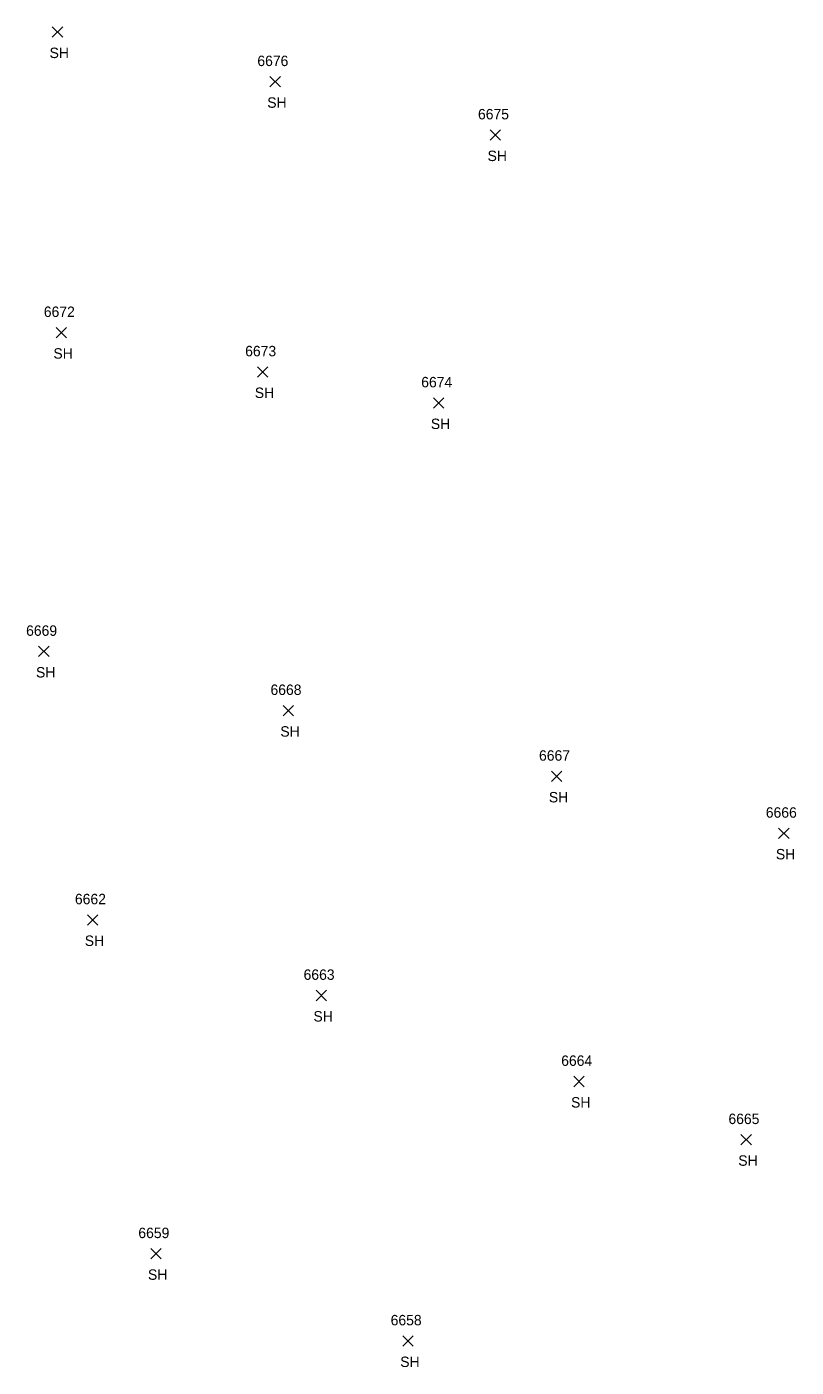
# Model space of a CAD drawing. Extents: x 1678863 to 1683592, y 407783 to 418211.
# Drawn here: x 1679579.6 to 1679727.2, y 410040.3 to 410297.6 of the extents above; entities that cross this region are included whole.
import ezdxf

# ---------------------------------------------------------------- set-up
doc = ezdxf.new("R2010")
doc.units = 0
for name, color, linetype in [('L_A', 7, 'Continuous'), ('L_I', 7, 'Continuous'), ('L_TIC', 7, 'Continuous')]:
    doc.layers.add(name, color=color, linetype=linetype)

msp = doc.modelspace()

# ---------------------------------------------------------------- linework, layer by layer
at = {"layer": 'L_TIC'}
for points in [[(1679584.46, 410295.56), (1679586.46, 410297.56)], [(1679586.46, 410295.56), (1679584.46, 410297.56)], [(1679626.23, 410286.02), (1679628.23, 410288.02)], [(1679628.23, 410286.02), (1679626.23, 410288.02)], [(1679668.51, 410275.79), (1679670.51, 410277.79)], [(1679670.51, 410275.79), (1679668.51, 410277.79)], [(1679585.19, 410237.87), (1679587.19, 410239.87)], [(1679587.19, 410237.87), (1679585.19, 410239.87)], [(1679623.84, 410230.32), (1679625.84, 410232.32)], [(1679625.84, 410230.32), (1679623.84, 410232.32)], [(1679657.62, 410224.36), (1679659.62, 410226.36)], [(1679659.62, 410224.36), (1679657.62, 410226.36)], [(1679581.85, 410176.67), (1679583.85, 410178.67)], [(1679583.85, 410176.67), (1679581.85, 410178.67)], [(1679628.75, 410165.32), (1679630.75, 410167.32)], [(1679630.75, 410165.32), (1679628.75, 410167.32)], [(1679680.27, 410152.7), (1679682.27, 410154.7)], [(1679682.27, 410152.7), (1679680.27, 410154.7)], [(1679723.85, 410141.76), (1679725.85, 410143.76)], [(1679725.85, 410141.76), (1679723.85, 410143.76)], [(1679591.21, 410125.15), (1679593.21, 410127.15)], [(1679593.21, 410125.15), (1679591.21, 410127.15)], [(1679635.09, 410110.64), (1679637.09, 410112.64)], [(1679637.09, 410110.64), (1679635.09, 410112.64)], [(1679684.53, 410094.13), (1679686.53, 410096.13)], [(1679686.53, 410094.13), (1679684.53, 410096.13)], [(1679716.63, 410082.96), (1679718.63, 410084.96)], [(1679718.63, 410082.96), (1679716.63, 410084.96)], [(1679603.35, 410061.07), (1679605.35, 410063.07)], [(1679605.35, 410061.07), (1679603.35, 410063.07)], [(1679651.75, 410044.33), (1679653.75, 410046.33)], [(1679653.75, 410044.33), (1679651.75, 410046.33)]]:
    msp.add_lwpolyline(points, dxfattribs=at)

# ---------------------------------------------------------------- texts
at = {"layer": 'L_A'}
for p in [(1679583.95, 410291.56), (1679625.72, 410282.02), (1679668, 410271.79), (1679584.68, 410233.87), (1679623.33, 410226.32), (1679657.11, 410220.36), (1679581.34, 410172.67), (1679628.23, 410161.32), (1679679.76, 410148.7), (1679723.33, 410137.76), (1679590.7, 410121.15), (1679634.58, 410106.64), (1679684.02, 410090.13), (1679716.11, 410078.96), (1679602.83, 410057.07), (1679651.24, 410040.33)]:
    msp.add_text('SH', height=2, dxfattribs=at).set_placement(p)
at = {"layer": 'L_I'}
for s, p in [('6676', (1679623.82, 410290.02)), ('6675', (1679666.16, 410279.79)), ('6672', (1679582.84, 410241.87)), ('6673', (1679621.48, 410234.32)), ('6674', (1679655.27, 410228.36)), ('6669', (1679579.44, 410180.67)), ('6668', (1679626.34, 410169.32)), ('6667', (1679677.87, 410156.7)), ('6666', (1679721.39, 410145.76)), ('6662', (1679588.81, 410129.15)), ('6663', (1679632.69, 410114.64)), ('6664', (1679682.13, 410098.13)), ('6665', (1679714.22, 410086.96)), ('6659', (1679600.98, 410065.07)), ('6658', (1679649.4, 410048.33))]:
    msp.add_text(s, height=2, dxfattribs=at).set_placement(p)

doc.saveas('drawing.dxf')
